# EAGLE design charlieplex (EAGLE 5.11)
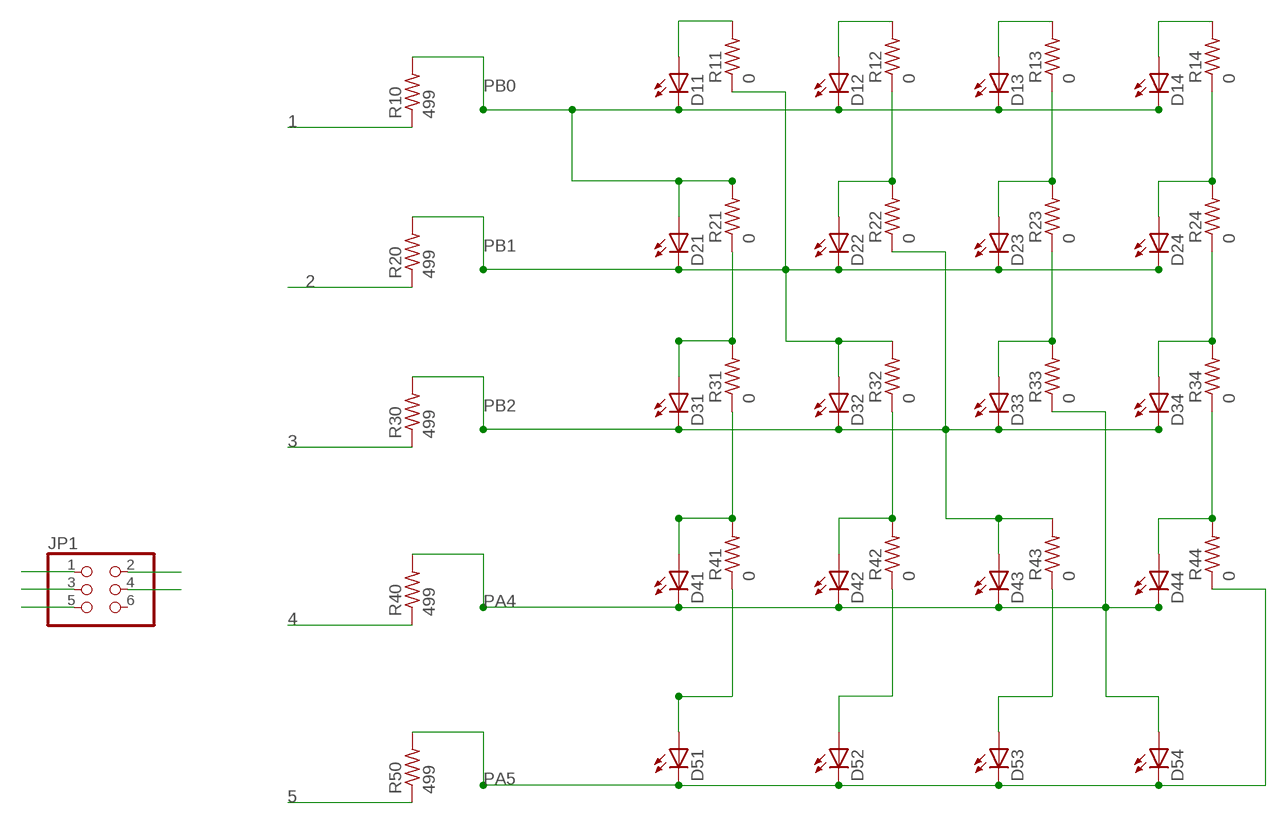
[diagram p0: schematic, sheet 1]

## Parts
D11  LED1206  [1206]
D12  LED1206  [1206]
D13  LED1206  [1206]
D14  LED1206  [1206]
D21  LED1206  [1206]
D22  LED1206  [1206]
D23  LED1206  [1206]
D24  LED1206  [1206]
D31  LED1206  [1206]
D32  LED1206  [1206]
D33  LED1206  [1206]
D34  LED1206  [1206]
D41  LED1206  [1206]
D42  LED1206  [1206]
D43  LED1206  [1206]
D44  LED1206  [1206]
D51  LED1206  [1206]
D52  LED1206  [1206]
D53  LED1206  [1206]
D54  LED1206  [1206]
JP1  PINHD-2X3-SMD  [2X03SMD]
R10  499  RESISTOR1206  [1206]
R11  0  RESISTOR1206  [1206]
R12  0  RESISTOR1206  [1206]
R13  0  RESISTOR1206  [1206]
R14  0  RESISTOR1206  [1206]
R20  499  RESISTOR1206  [1206]
R21  0  RESISTOR1206  [1206]
R22  0  RESISTOR1206  [1206]
R23  0  RESISTOR1206  [1206]
R24  0  RESISTOR1206  [1206]
R30  499  RESISTOR1206  [1206]
R31  0  RESISTOR1206  [1206]
R32  0  RESISTOR1206  [1206]
R33  0  RESISTOR1206  [1206]
R34  0  RESISTOR1206  [1206]
R40  499  RESISTOR1206  [1206]
R41  0  RESISTOR1206  [1206]
R42  0  RESISTOR1206  [1206]
R43  0  RESISTOR1206  [1206]
R44  0  RESISTOR1206  [1206]
R50  499  RESISTOR1206  [1206]

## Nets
1: JP1.1 R10.1
2: JP1.2 R20.1
3: JP1.3 R30.1
4: JP1.4 R40.1
5: JP1.5 R50.1
N$6: D31.1(A) R21.1 R31.2
N$9: D41.1(A) R31.1 R41.2
N$19: D51.1(A) R41.1
N$20: D42.1(A) R32.1 R42.2
N$21: D52.1(A) R42.1
N$22: D53.1(A) R43.1
N$26: D11.1(A) R11.2
N$27: D22.1(A) R12.1 R22.2
N$28: D12.1(A) R12.2
N$29: D33.1(A) R23.1 R33.2
N$30: D23.1(A) R13.1 R23.2
N$31: D13.1(A) R13.2
N$32: D44.1(A) R34.1 R44.2
N$33: D34.1(A) R24.1 R34.2
N$34: D24.1(A) R14.1 R24.2
N$35: D14.1(A) R14.2
PA4: D41.2(C) D42.2(C) D43.2(C) D44.2(C) D54.1(A) R33.1 R40.2
PA5: D51.2(C) D52.2(C) D53.2(C) D54.2(C) R44.1 R50.2
PB0: D11.2(C) D12.2(C) D13.2(C) D14.2(C) D21.1(A) R10.2 R21.2
PB1: D21.2(C) D22.2(C) D23.2(C) D24.2(C) D32.1(A) R11.1 R20.2 R32.2
PB2: D31.2(C) D32.2(C) D33.2(C) D34.2(C) D43.1(A) R22.1 R30.2 R43.2
Unconnected: JP1.6

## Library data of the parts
D11-D14 D21-D24 D31-D34 D41-D44 D51-D54 = ng:LED
JP1 = fab:PINHD-2X3-SMD: PIN HEADER
R10-R14 R20-R24 R30-R34 R40-R44 R50 = ng:RESISTOR

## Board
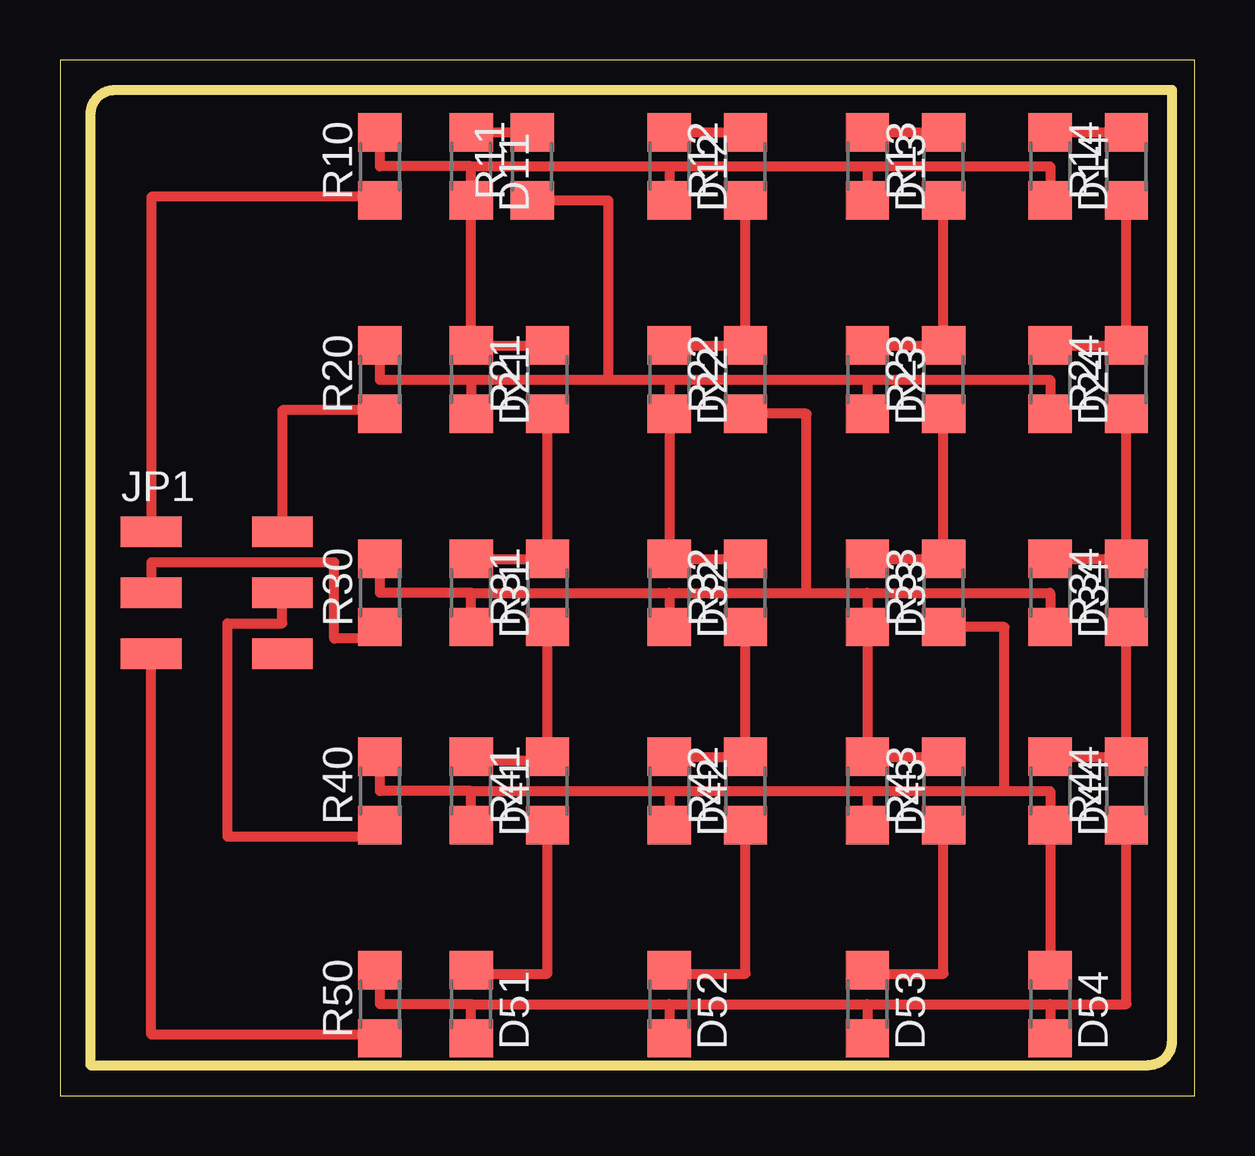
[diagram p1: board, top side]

Size 47.3 x 43.17 mm. Coordinates in mm from the lower left corner, seen from the top.
Outline: 0,0 47.3,0 47.3,43.17 0,43.17 0,0
Copper layers 1: Top 0.035mm
Design rules "ERP-1sided-10mil-16mill": minimum track width 10mil, minimum drill 24mil, track to track 16mil, track to pad 16mil, pad to pad 16mil, via to via 16mil, smd to smd 0mil, copper to edge 16mil, drill to drill 36mil, minimum pad ring 10mil, minimum via ring 8mil, stop-mask expansion 4mil, vias tented up to drill 0mil, thermal gap 10mil
Milling: area 1.3,1.3 to 46.4,41.9

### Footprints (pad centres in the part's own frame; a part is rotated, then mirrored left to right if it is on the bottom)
1206 = smd 1.6 x 1.803: 1 -1.422,0; 2 1.422,0
2X03SMD = smd 2.54 x 1.27: 1 -2.54,2.54; 2 2.92,2.54; 3 -2.54,0; 4 2.92,0; 5 -2.54,-2.54; 6 2.92,-2.54

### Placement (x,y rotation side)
D11  17.14,38.73 270 top
D12  25.4,38.73 270 top
D13  33.66,38.73 270 top
D14  41.27,38.73 270 top
D21  17.14,29.84 270 top
D22  25.4,29.84 270 top
D23  33.66,29.84 270 top
D24  41.27,29.84 270 top
D31  17.14,20.95 270 top
D32  25.4,20.95 270 top
D33  33.66,20.95 270 top
D34  41.27,20.95 270 top
D41  17.14,12.7 270 top
D42  25.4,12.7 270 top
D43  33.66,12.7 270 top
D44  41.27,12.7 270 top
D51  17.14,3.81 270 top
D52  25.4,3.81 270 top
D53  33.66,3.81 270 top
D54  41.27,3.81 270 top
JP1  6.35,20.95 0 top
R10  13.34,38.73 90 top
R11  19.68,38.73 90 top
R12  28.57,38.73 90 top
R13  36.83,38.73 90 top
R14  44.45,38.73 90 top
R20  13.34,29.84 90 top
R21  20.32,29.84 90 top
R22  28.57,29.84 90 top
R23  36.83,29.84 90 top
R24  44.45,29.84 90 top
R30  13.34,20.95 90 top
R31  20.32,20.95 90 top
R32  28.57,20.95 90 top
R33  36.83,20.95 90 top
R34  44.45,20.95 90 top
R40  13.34,12.7 90 top
R41  20.32,12.7 90 top
R42  28.57,12.7 90 top
R43  36.83,12.7 90 top
R44  44.45,12.7 90 top
R50  13.34,3.81 90 top

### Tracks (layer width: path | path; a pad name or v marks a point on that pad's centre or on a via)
1
  Top 0.406: R10.1 13.34,37.47 3.81,37.47 JP1.1
2
  Top 0.406: R20.1 13.34,28.57 9.27,28.57 JP1.2
3
  Top 0.406: R30.1 13.34,19.05 11.43,19.05 11.43,22.23 3.81,22.23 JP1.3
4
  Top 0.406: R40.1 13.34,10.79 6.99,10.79 6.99,19.68 9.27,19.68 JP1.4
5
  Top 0.406: R50.1 13.34,2.54 3.81,2.54 JP1.5
N$6
  Top 0.406: R21.1 R31.2 D31.1
N$9
  Top 0.406: R31.1 R41.2 20.32,13.97 17.14,13.97 D41.1
N$19
  Top 0.406: R41.1 20.32,5.08 17.14,5.08 D51.1
N$20
  Top 0.406: R32.1 R42.2 D42.1
N$21
  Top 0.406: R42.1 28.57,5.08 25.4,5.08 | 24.77,5.08 25.4,5.08 | 25.4,5.08 D52.1
N$22
  Top 0.406: R43.1 36.83,5.08 33.66,5.08 D53.1
N$26
  Top 0.406: D11.1 R11.2
N$27
  Top 0.406: D22.1 R22.2 R12.1
N$28
  Top 0.406: D12.1 R12.2
N$29
  Top 0.406: D33.1 R33.2 R23.1 | D33.1 33.02,22.38 33.02,22.23 33.66,22.23 D33.1
N$30
  Top 0.406: D23.1 R23.2 R13.1
N$31
  Top 0.406: D13.1 R13.2
N$32
  Top 0.406: D44.1 R44.2 R34.1
N$33
  Top 0.406: D34.1 R34.2 R24.1
N$34
  Top 0.406: D24.1 R24.2 R14.1
N$35
  Top 0.406: D14.1 R14.2 | R14.2 45.09,40.16 45.09,40.01 44.45,40.01 R14.2
PA4
  Top 0.406: R40.2 13.34,12.7 17.14,12.7 | D41.2 17.14,12.7 | 17.14,12.7 25.4,12.7 | 25.4,12.7 33.66,12.7 | 33.66,12.7 39.37,12.7 | 39.37,12.7 41.27,12.7 D44.2 D54.1 | 33.66,12.7 D43.2 | 25.4,12.7 D42.2 | R33.1 39.37,19.53 39.37,12.7
PA5
  Top 0.406: R50.2 13.34,3.81 17.14,3.81 | D51.2 17.14,3.81 | 17.14,3.81 25.4,3.81 | 25.4,3.81 33.66,3.81 | 33.66,3.81 41.27,3.81 | 41.27,3.81 D54.2 | 33.66,3.81 D53.2 | 25.4,3.81 D52.2 | R44.1 44.45,3.81 41.27,3.81
PB0
  Top 0.406: R10.2 13.34,38.73 17.14,38.73 | 25.4,38.73 D12.2 | 33.66,38.73 D13.2 | D14.2 41.27,38.73 33.66,38.73 | 25.4,38.73 33.66,38.73 | 17.14,38.73 D11.2 D21.1 R21.2 | 17.14,38.73 25.4,38.73
PB1
  Top 0.406: R20.2 13.34,29.84 17.14,29.84 | 17.14,29.84 D21.2 | 17.14,29.84 22.86,29.84 | 22.86,29.84 25.4,29.84 | 25.4,29.84 33.66,29.84 | 33.66,29.84 41.27,29.84 D24.2 | 33.66,29.84 D23.2 | 25.4,29.84 D22.2 D32.1 R32.2 | R11.1 22.86,37.31 22.86,29.84
PB2
  Top 0.406: R30.2 13.34,20.95 17.14,20.95 | D31.2 17.14,20.95 | 17.14,20.95 25.4,20.95 | 25.4,20.95 31.11,20.95 | 31.11,20.95 33.66,20.95 | 33.66,20.95 41.27,20.95 D34.2 | 33.66,20.95 D33.2 D43.1 R43.2 | 25.4,20.95 D32.2 | R22.1 31.11,28.42 31.11,20.95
